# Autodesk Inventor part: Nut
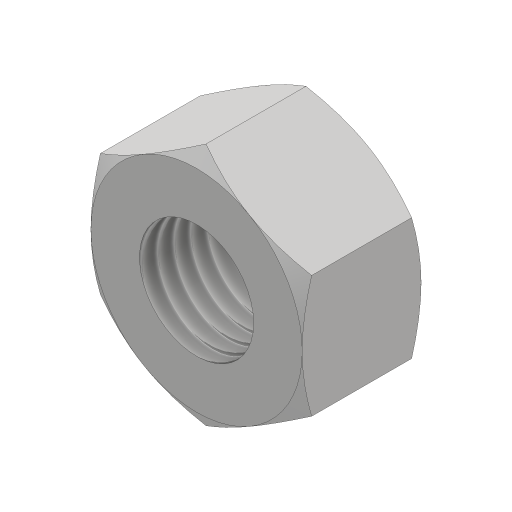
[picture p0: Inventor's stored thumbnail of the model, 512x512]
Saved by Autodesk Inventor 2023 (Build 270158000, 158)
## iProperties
Created: 2016-05
Part Number: Nut
Material: Generic
Document SubType Name: Modeling
Designer: CADCIM
Density: 1 g/cm^3
Appearance: Default
Author: CADCIM
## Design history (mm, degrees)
sketch "Sketch1"
  geometry: L1 (9.6, -5.543)-(0, -11.085); L2 (0, -11.085)-(-9.6, -5.543); L3 (-9.6, -5.543)-(-9.6, 5.543); L4 (-9.6, 5.543)-(0, 11.085); L5 (0, 11.085)-(9.6, 5.543); L6 (9.6, 5.543)-(9.6, -5.543); 2 further points
  constraints: 12 end point, 1 coincident, 1 vertical alignment, 13 other
  dimensions: "d0" = 19.2 distance between parallel lines of L3 L6
extrude "Extrusion1" new body sketch "Sketch1" distance "d1" = 10.8; taper "d2" = 0 deg
sketch "Sketch2"
  geometry: L1 (0, 11.085)-(-9.6, 5.543) reference; C1 r 9.6 at (0, 0); 1 further point
  constraints: 1 centre point, 1 coincident, 1 tangent
extrude "Extrusion2" sketch "Sketch2" distance "d3" = 10.8; taper "d4" = 60 deg
workplane "Work Plane1"
sketch "Sketch3"
  geometry: L1 (0, -11.085)-(9.6, -5.543) reference; C1 r 9.6 at (0, 0); 1 further point
  constraints: 1 centre point, 1 coincident, 1 tangent
extrude "Extrusion3" sketch "Sketch3" distance "d5" = 10.8; taper "d6" = 60 deg
sketch "Sketch4"
  geometry: 1 further point
hole "Hole1" diameter "d9" = 10.376; stored, may be unused: countersink angle "d13" = 90 deg, drill point angle "d15" = 118 deg; dims "d7" = 10, "d8" = 10, "d10" = 24, "d11" = 4, "d12" = 2, "d14" = 31.3
body "Solid1"
